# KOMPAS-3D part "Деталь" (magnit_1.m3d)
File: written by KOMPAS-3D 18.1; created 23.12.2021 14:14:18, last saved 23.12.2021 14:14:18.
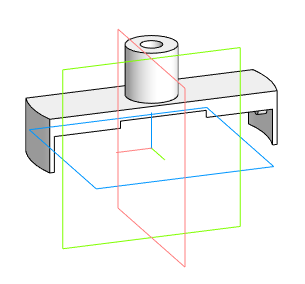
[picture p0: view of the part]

Document properties: Автор: 111; Полное имя файла: C:\Users\admin\Desktop\ffb\magnit_1.m3d

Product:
- Part/product: Деталь

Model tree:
1. Операция без истории:1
